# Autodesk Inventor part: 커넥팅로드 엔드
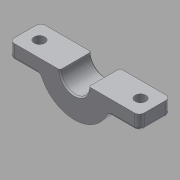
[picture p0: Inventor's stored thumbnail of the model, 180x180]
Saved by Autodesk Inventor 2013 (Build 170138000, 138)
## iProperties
Created: 2016-11
Part Number: 커넥팅로드 엔드
Material: 알루미늄 6061
Document SubType Name: Modeling
Designer: mduedu
Density: 2.71 g/cm^3
Mass: 15.0819 g
Surface Area: 26.6719 cm^2
Volume: 5.56529 cm^3
Author: mduedu
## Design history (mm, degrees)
sketch "스케치1" dims "d0" = 30, "d3" = 15
  geometry: L1 (0, 0)-(0, 96); L2 (-5, 90.41)-(-10, 11.18); L3 (5, 90.41)-(10, 11.18); C1 r 6 at (0, 0); C2 r 4 at (0, 96); 3 further points
  constraints: 6 end point, 4 coincident, 2 centre point, 2 symmetric about line, 1 vertical, 6 other
  dimensions: "d1" = 12 diameter of C1; "d2" = 8 diameter of C2; "d4" = 96 distance of L1.start L1.end; "d6" = 10 distance from line of L1 L2.end; "d7" = 5 distance from line of L1 L2.start
extrude "돌출1" new body sketch "스케치1" stored distance "d8" = 13; taper "d9" = 0 deg
extrude "돌출2" join sketch "스케치1" stored distance "d10" = 32; taper "d11" = 0 deg
sketch "스케치2"
  geometry: L1 (5, 90.41)-(10, 11.18) reference; L2 (-5, 90.41)-(-10, 11.18) reference; A1 r 7.5 centre (0, 96) between (5, 90.41) and (-5, 90.41) reference; A2 r 15 centre (0, 0) between (10, 11.18) and (-10, 11.18) reference
extrude "돌출3" join sketch "스케치2" stored distance "d12" = 8; taper "d13" = 0 deg
sketch "스케치3"
  geometry: L1 (-2.732, 78.715)-(-6.171, 24.226); L2 (2.732, 78.715)-(6.171, 24.226); L3 (0, 78.5)-(0, 25); A1 r 17.5 centre (0, 96) between (-2.732, 78.715) and (2.732, 78.715); A2 r 25 centre (0, 0) between (6.171, 24.226) and (-6.171, 24.226); 9 further points; 2 other entities
  constraints: 6 end point, 6 point on circle, 2 centre point, 1 symmetric about line, 1 vertical alignment, 6 other
  dimensions: "d18" = 10 dimension on A1; "d19" = 10 dimension on A2; "d20" = 3 dimension on L1
extrude "돌출4" cut sketch "스케치3" distance "d21" = 2; taper "d22" = 0 deg
fillet "모깎기1" dims "d23" = 2
fillet "모깎기2" dims "d24" = 2
fillet "모깎기3" dims "d25" = 1
chamfer "모따기1" distance "d26" = 0.5; stored, may be unused: second distance "d27" = 2, angle "d28" = 45 deg
sketch "스케치4"
  geometry: L1 (-27, -6)-(-13.748, -6); L2 (27, -6)-(27, 6); L3 (27, 6)-(13.748, 6); L4 (-27, 6)-(-27, -6); L5 (-27, -6)-(27, 6); L6 (27, -6)-(-27, 6); L7 (-13.748, 6)-(-27, 6); L8 (13.748, 6)-(-13.748, 6); L9 (13.748, -6)-(27, -6); L10 (-13.748, -6)-(13.748, -6); A1 r 15 centre (0, 0) between (-13.748, 6) and (13.748, 6) reference; 1 further point
  constraints: 20 end point, 10 parallel, 4 point on circle, 3 horizontal, 3 perpendicular, 2 midpoint
  dimensions: "d29" = 54 distance of L1.start L2.start; "d31" = 12 distance of L2.start L2.end
extrude "돌출5" join sketch "스케치4" stored distance "d32" = 0; taper "d33" = 0 deg
fillet "모깎기4" dims "d34" = 2
fillet "모깎기5" dims "d35" = 1
fillet "모깎기6" dims "d36" = 1
sketch "스케치5"
  geometry: L1 (1, 0)-(1, 9) reference; L2 (-18.5, 20.5)-(-33.5, 20.5) reference; L3 (-33.5, -11.5)-(-18.5, -11.5) reference; L4 (-26, 20.5)-(-26, -11.5); 3 further points
  constraints: 2 end point, 2 midpoint, 1 horizontal alignment, 1 symmetric about line
  dimensions: "d37" = 6 distance from line of point (-5, 4.5) L1
feature "분할1"
sketch "스케치7"
  geometry: 2 further points
  constraints: 2 other
hole "구멍2" sketch "스케치7" at (-47, 4.5), (-5, 4.5) diameter "d45" = 4.5; stored, may be unused: countersink angle "d49" = 90 deg, drill point angle "d51" = 0 deg; dims "d46" = 6, "d47" = 4, "d48" = 2, "d50" = 8
node "솔리드1"
mirror "대칭1"
other parameters: "d16" = 4, "d17" = 4
